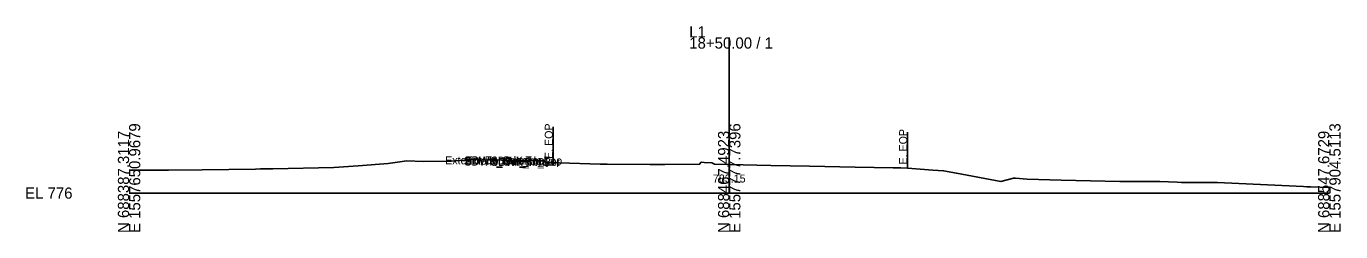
# Model space of a CAD drawing. Extents: x -26 to 2603, y -3010 to 9589.
# Drawn here: x -25.7 to 302.8, y 1990.3 to 2041.8 of the extents above; entities that cross this region are included whole.
import ezdxf

# ---------------------------------------------------------------- set-up
doc = ezdxf.new("R2010")
doc.units = 0
for name, color, linetype in [('Default', 7, 'Continuous'), ('Exist Cross Section Cell', 7, 'Continuous'), ('Exist XS Center Line Elevation Label', 7, 'Continuous'), ('Exist XS Ground Line', 7, 'Continuous'), ('Prop CMT Conc Surface', 7, 'Continuous'), ('Prop CMT Concrete Structures', 7, 'Continuous'), ('Prop XS Earthwork Shape', 7, 'Continuous'), ('Prop XS Label Text', 7, 'Continuous')]:
    doc.layers.add(name, color=color, linetype=linetype)

msp = doc.modelspace()

# ---------------------------------------------------------------- linework, layer by layer
at = {"layer": 'Exist Cross Section Cell'}
for p, q in [((150, 2000), (150, 2039)), ((0, 2000), (150, 2000)), ((150, 2000), (300, 2000))]:
    msp.add_line(p, q, dxfattribs=at)
at = {"layer": 'Exist XS Ground Line'}
msp.add_lwpolyline([(0, 2005.71), (9.84, 2005.73), (18.25, 2005.81), (31.63, 2006.03), (32.87, 2006.04), (33.65, 2006.06), (35.89, 2006.1), (51.17, 2006.37), (57.23, 2006.79), (64.75, 2007.44), (69.43, 2008.06), (73.5, 2007.92), (80.58, 2007.96), (83.83, 2008.27), (85.61, 2008.52), (87.01, 2008.33), (99.14, 2008.14), (102.05, 2008.05), (103.58, 2008.04), (104.27, 2007.57), (106.02, 2007.66), (107.49, 2007.61), (117.75, 2007.25), (119.46, 2007.23), (130.19, 2007.12), (133.89, 2007.15), (142.61, 2007.24), (142.95, 2007.74), (143.72, 2007.7), (145.67, 2007.6), (146.35, 2007.22), (150, 2007.15), (160.44, 2006.95), (170.08, 2006.76), (181.5, 2006.53), (190.96, 2006.36), (192.91, 2006.3), (194.57, 2006.23), (200.9, 2005.77), (203.6, 2005.59), (206.78, 2004.96), (217.93, 2002.91), (221.04, 2003.75), (221.57, 2003.73), (224.43, 2003.45), (232.94, 2003.24), (247.67, 2002.93), (251.77, 2002.91), (257.59, 2002.87), (262, 2002.74), (263.08, 2002.67), (264.42, 2002.68), (272.07, 2002.62), (291.7, 2001.72), (293.5, 2001.63), (294.35, 2001.59), (295.32, 2001.55), (300, 2001.38)], dxfattribs=at)
at = {"layer": 'Prop CMT Conc Surface'}
msp.add_line((99.84, 2008.12), (94.84, 2008.21), dxfattribs=at)
for points in [[(104, 2007.54), (104, 2008.04), (103.5, 2008.04)], [(106, 2007.66), (104, 2007.54)]]:
    msp.add_lwpolyline(points, dxfattribs=at)
at = {"layer": 'Prop CMT Concrete Structures'}
msp.add_line((99.84, 2007.79), (94.84, 2007.88), dxfattribs=at)
for points in [[(94.84, 2007.88), (94.84, 2008.21)], [(99.84, 2008.12), (99.84, 2007.79)], [(103.5, 2008.04), (103.5, 2007.03), (106, 2007.08)], [(106, 2007.08), (106, 2007.66)]]:
    msp.add_lwpolyline(points, dxfattribs=at)
at = {"layer": 'Prop XS Earthwork Shape'}
for points in [[(99.84, 2008.12), (94.84, 2008.21), (94.84, 2007.88), (99.84, 2007.79)], [(99.84, 2008.12), (94.84, 2008.21), (99.14, 2008.14)]]:
    msp.add_lwpolyline(points, close=True, dxfattribs=at)
at = {"layer": 'Prop XS Label Text'}
for p, q in [((106, 2016.61), (106, 2007.61)), ((194.57, 2015.23), (194.57, 2006.23))]:
    msp.add_line(p, q, dxfattribs=at)

# ---------------------------------------------------------------- texts
at = {"layer": 'Default'}
for s, height, p in [('Exterior Boundary', 2, (78.99, 2007.22)), ('SDWK_Out_Top', 2, (83.77, 2007.22)), ('SDWK_Out_Bot', 2, (83.8, 2006.89)), ('Exterior Boundary', 2, (83.99, 2007.12)), ('SDWK_In_Top', 2, (90.4, 2007.12)), ('SDWK_In_Bot', 2, (90.43, 2006.79)), ('-', 0.0001, (0, 2000))]:
    msp.add_text(s, height=height, dxfattribs=at).set_placement(p)
at = {"layer": 'Exist Cross Section Cell'}
for s, p in [('L1', (140, 2039)), ('18+50.00 / 1', (140, 2036.2)), ('EL 776', (-26, 1998.6))]:
    msp.add_text(s, height=2.8, dxfattribs=at).set_placement(p)
for s, p in [('E 1557650.9679', (2.8, 1990)), ('E 1557777.7396', (152.8, 1990)), ('E 1557904.5113', (302.8, 1990)), ('N 688387.3117', (0, 1990)), ('N 688467.4923', (150, 1990)), ('N 688547.6729', (300, 1990))]:
    msp.add_text(s, height=2.8, rotation=90, dxfattribs=at).set_placement(p)
at = {"layer": 'Exist XS Center Line Elevation Label'}
msp.add_text('783.15', height=2, dxfattribs=at).set_placement((145.92, 2002.65))
at = {"layer": 'Prop XS Label Text'}
for p in [(105.9, 2008.53), (194.47, 2007.15)]:
    msp.add_text('E. EOP', height=2, rotation=90, dxfattribs=at).set_placement(p)

doc.saveas('drawing.dxf')
